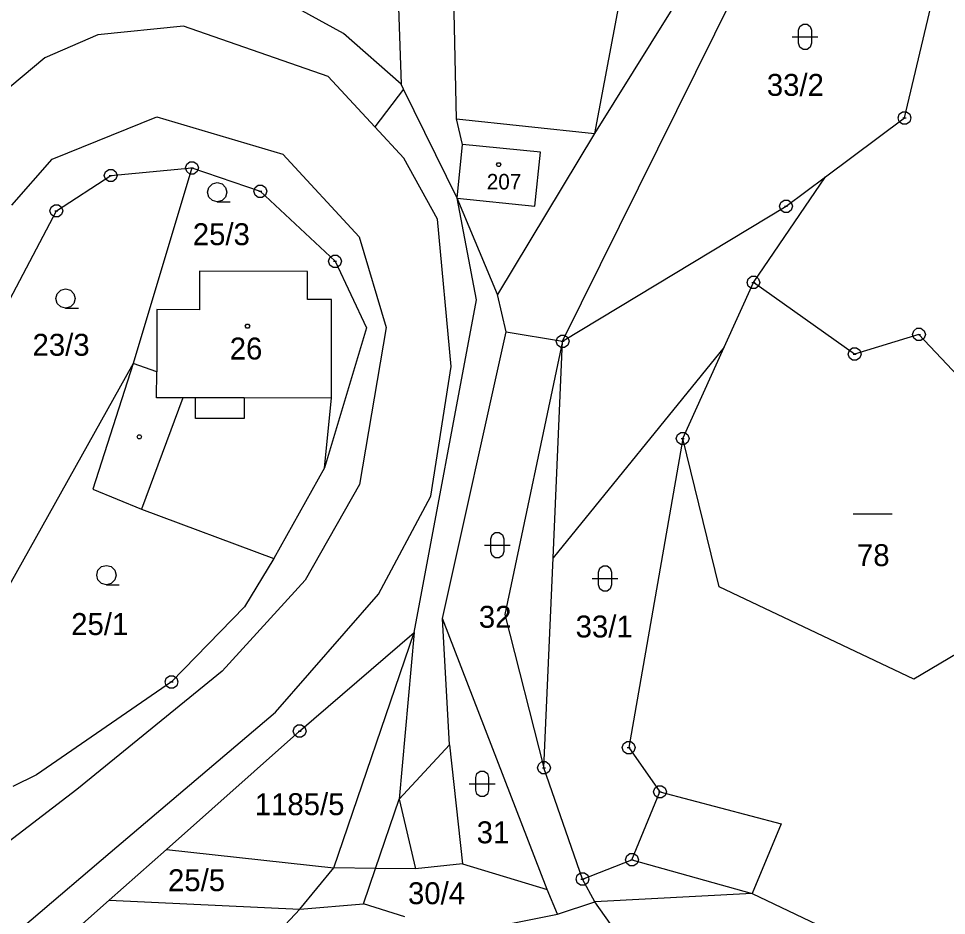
# Model space of a CAD drawing. Extents: x -694465 to -690527, y -983694 to -978978.
# Drawn here: x -691805.9 to -691734, y -981057 to -980987.5 of the extents above; entities that cross this region are included whole.
import ezdxf

# ---------------------------------------------------------------- set-up
doc = ezdxf.new("R2010")
doc.units = 0
for name, color, linetype in [('Vrstva 1', 7, 'Continuous'), ('Vrstva 18', 7, 'Continuous'), ('Vrstva 19', 7, 'Continuous'), ('Vrstva 24', 7, 'Continuous'), ('Vrstva 25', 7, 'Continuous')]:
    doc.layers.add(name, color=color, linetype=linetype)

msp = doc.modelspace()

# ---------------------------------------------------------------- linework, layer by layer
at = {"layer": 'Vrstva 1'}
for points in [[(-691753.27, -980956.49), (-691754.479, -980963.964), (-691753.869, -980984.579), (-691761.25, -980996.4)], [(-691757.32, -980975.53), (-691761.25, -980996.4)], [(-691776.7, -980979.2), (-691776.23, -980992.59)], [(-691771.95, -980995.28), (-691772.18, -980984.63)], [(-691780.69, -980988.65), (-691785.28, -980986.14)], [(-691763.71, -981012.51), (-691750.43, -980985.69)], [(-691737.21, -980995.2), (-691735.16, -980986.59)], [(-691793.09, -980988.08), (-691799.74, -980988.76)], [(-691781.88, -980991.99), (-691793.09, -980988.08)], [(-691799.74, -980988.76), (-691803.84, -980990.55)], [(-691776.23, -980992.59), (-691780.69, -980988.65)], [(-691803.84, -980990.55), (-691809.14, -980994.97)], [(-691778.265, -980995.895), (-691781.88, -980991.99)], [(-691776.037, -980992.983), (-691776.23, -980992.59)], [(-691776.037, -980992.983), (-691778.265, -980995.895)], [(-691771.9, -981001.43), (-691776.037, -980992.983)], [(-691803.27, -980998.4), (-691795.18, -980995.12)], [(-691795.18, -980995.12), (-691785.4, -980998.02)], [(-691771.47, -980997.25), (-691771.95, -980995.28)], [(-691771.95, -980995.28), (-691761.25, -980996.4)], [(-691743.34, -980999.77), (-691737.21, -980995.2)], [(-691776.03, -980998.31), (-691778.265, -980995.895)], [(-691761.25, -980996.4), (-691768.75, -981008.88)], [(-691771.9, -981001.43), (-691771.47, -980997.25)], [(-691765.44, -980997.86), (-691771.47, -980997.25)], [(-691765.86, -981002.04), (-691765.44, -980997.86)], [(-691806.4, -981001.96), (-691803.27, -980998.4)], [(-691785.4, -980998.02), (-691779.48, -981004.42)], [(-691773.41, -981003.05), (-691776.03, -980998.31)], [(-691809.08, -981022.44), (-691807.08, -981010.25), (-691802.95, -981002.4), (-691798.74, -980999.66), (-691792.45, -980999.07)], [(-691792.45, -980999.07), (-691797, -981014.23)], [(-691792.45, -980999.07), (-691787.15, -981000.88)], [(-691748.92, -981007.95), (-691743.34, -980999.77)], [(-691746.39, -981002.05), (-691743.34, -980999.77)], [(-691787.15, -981000.88), (-691781.35, -981006.31), (-691778.92, -981011.46), (-691782.16, -981022.32)], [(-691768.75, -981008.88), (-691771.9, -981001.43)], [(-691771.9, -981001.43), (-691765.86, -981002.04)], [(-691770.4, -981009.3), (-691771.9, -981001.43)], [(-691763.71, -981012.51), (-691746.39, -981002.05)], [(-691772.36, -981014.46), (-691773.41, -981003.05)], [(-691779.48, -981004.42), (-691777.39, -981011.44)], [(-691791.85, -981007.08), (-691791.86, -981010.06)], [(-691783.49, -981007.09), (-691791.85, -981007.08)], [(-691783.49, -981009.28), (-691783.49, -981007.09)], [(-691751.188, -981012.953), (-691748.92, -981007.95)], [(-691741.08, -981013.5), (-691748.92, -981007.95)], [(-691781.63, -981009.28), (-691783.49, -981009.28)], [(-691781.64, -981016.91), (-691781.63, -981009.28)], [(-691775.21, -981035.08), (-691770.4, -981009.3)], [(-691768.09, -981011.77), (-691768.75, -981008.88)], [(-691791.86, -981010.06), (-691795.18, -981010.05)], [(-691795.18, -981010.05), (-691795.18, -981014.87)], [(-691777.39, -981011.44), (-691779.46, -981023.61)], [(-691773.02, -981034), (-691768.09, -981011.77)], [(-691768.09, -981011.77), (-691763.71, -981012.51)], [(-691736.09, -981011.98), (-691741.08, -981013.5)], [(-691725.69, -981023), (-691736.09, -981011.98)], [(-691763.71, -981012.51), (-691768.2, -981033.672), (-691765.16, -981045.56)], [(-691764.446, -981029.294), (-691763.71, -981012.51)], [(-691751.188, -981012.953), (-691764.446, -981029.294)], [(-691754.4, -981020.04), (-691751.188, -981012.953)], [(-691797, -981014.23), (-691807.08, -981032.26)], [(-691797, -981014.23), (-691800.14, -981023.98)], [(-691795.18, -981014.87), (-691797, -981014.23)], [(-691795.19, -981016.89), (-691795.18, -981014.87)], [(-691773.92, -981024.52), (-691772.36, -981014.46)], [(-691793.15, -981016.89), (-691796.35, -981025.53)], [(-691793.15, -981016.89), (-691795.19, -981016.89)], [(-691792.16, -981016.9), (-691793.15, -981016.89)], [(-691788.4, -981016.9), (-691792.16, -981016.9)], [(-691792.16, -981018.49), (-691792.16, -981016.9)], [(-691781.64, -981016.91), (-691788.4, -981016.9)], [(-691788.4, -981016.9), (-691788.4, -981018.49)], [(-691782.16, -981022.32), (-691781.64, -981016.91)], [(-691788.4, -981018.49), (-691792.16, -981018.49)], [(-691754.4, -981020.04), (-691758.59, -981043.99)], [(-691751.59, -981031.54), (-691754.4, -981020.04)], [(-691782.16, -981022.32), (-691786.09, -981029.35)], [(-691779.46, -981023.61), (-691783.68, -981031.02)], [(-691800.14, -981023.98), (-691796.35, -981025.53)], [(-691777.99, -981032.1), (-691773.92, -981024.52)], [(-691796.35, -981025.53), (-691786.09, -981029.35)], [(-691786.09, -981029.35), (-691788.36, -981033.08)], [(-691765.16, -981045.56), (-691764.446, -981029.294)], [(-691783.68, -981031.02), (-691790.1, -981038.06)], [(-691736.5, -981038.69), (-691751.59, -981031.54)], [(-691785.98, -981041.25), (-691777.99, -981032.1)], [(-691788.36, -981033.08), (-691794.03, -981038.91), (-691804.49, -981046.11)], [(-691726.14, -981032.57), (-691736.5, -981038.69)], [(-691764.9, -981054.98), (-691773.02, -981034)], [(-691772.47, -981043.77), (-691773.02, -981034)], [(-691784.1, -981042.71), (-691775.21, -981035.08)], [(-691781.45, -981053.31), (-691775.21, -981035.08)], [(-691775.21, -981035.08), (-691776.39, -981047.99)], [(-691790.1, -981038.06), (-691801.38, -981047.23)], [(-691798.78, -981052.13), (-691785.98, -981041.25)], [(-691794.42, -981051.88), (-691784.1, -981042.71)], [(-691776.39, -981047.99), (-691772.47, -981043.77)], [(-691772.47, -981043.77), (-691771.47, -981053.01)], [(-691758.59, -981043.99), (-691756.17, -981047.42)], [(-691762.17, -981054.18), (-691765.16, -981045.56)], [(-691804.49, -981046.11), (-691806.34, -981047.02)], [(-691801.38, -981047.23), (-691816.93, -981059.15)], [(-691758.34, -981052.68), (-691756.17, -981047.42)], [(-691756.17, -981047.42), (-691746.76, -981049.89)], [(-691778.21, -981053.36), (-691776.39, -981047.99)], [(-691776.39, -981047.99), (-691775.12, -981053.4)], [(-691746.76, -981049.89), (-691749.02, -981055.3)], [(-691811.06, -981062.57), (-691798.78, -981052.13)], [(-691798.87, -981055.81), (-691794.42, -981051.88)], [(-691794.42, -981051.88), (-691781.45, -981053.31)], [(-691771.47, -981053.01), (-691775.12, -981053.4)], [(-691771.47, -981053.01), (-691764.9, -981054.98)], [(-691762.17, -981054.18), (-691758.34, -981052.68)], [(-691758.34, -981052.68), (-691749.02, -981055.3)], [(-691784.08, -981056.52), (-691781.45, -981053.31)], [(-691778.21, -981053.36), (-691781.45, -981053.31)], [(-691779.14, -981056.09), (-691778.21, -981053.36)], [(-691775.12, -981053.4), (-691778.21, -981053.36)], [(-691761.21, -981055.95), (-691762.17, -981054.18)], [(-691764.11, -981056.9), (-691764.9, -981054.98)], [(-691749.02, -981055.3), (-691761.21, -981055.95)], [(-691749.02, -981055.3), (-691722.7, -981067.85)], [(-691809.71, -981065.43), (-691798.87, -981055.81)], [(-691798.87, -981055.81), (-691784.08, -981056.52)], [(-691784.08, -981056.52), (-691779.14, -981056.09)], [(-691775.94, -981057.1), (-691779.14, -981056.09)], [(-691764.11, -981056.9), (-691761.21, -981055.95)], [(-691759.15, -981058.87), (-691761.21, -981055.95)], [(-691784.08, -981056.52), (-691791.64, -981064.58)], [(-691774.08, -981058.89), (-691764.11, -981056.9)]]:
    msp.add_lwpolyline(points, dxfattribs=at)
at = {"layer": 'Vrstva 24'}
for points in [[(-691737.056, -980994.724), (-691736.806, -980994.906), (-691736.71, -980995.2), (-691736.806, -980995.494), (-691737.056, -980995.676), (-691737.364, -980995.676), (-691737.614, -980995.494), (-691737.71, -980995.2), (-691737.614, -980994.906), (-691737.364, -980994.724)], [(-691798.586, -980999.184), (-691798.336, -980999.366), (-691798.24, -980999.66), (-691798.336, -980999.954), (-691798.586, -981000.136), (-691798.894, -981000.136), (-691799.144, -980999.954), (-691799.24, -980999.66), (-691799.144, -980999.366), (-691798.894, -980999.184)], [(-691792.296, -980998.594), (-691792.046, -980998.776), (-691791.95, -980999.07), (-691792.046, -980999.364), (-691792.296, -980999.546), (-691792.604, -980999.546), (-691792.854, -980999.364), (-691792.95, -980999.07), (-691792.854, -980998.776), (-691792.604, -980998.594)], [(-691786.996, -981000.404), (-691786.746, -981000.586), (-691786.65, -981000.88), (-691786.746, -981001.174), (-691786.996, -981001.356), (-691787.304, -981001.356), (-691787.554, -981001.174), (-691787.65, -981000.88), (-691787.554, -981000.586), (-691787.304, -981000.404)], [(-691802.796, -981001.924), (-691802.546, -981002.106), (-691802.45, -981002.4), (-691802.546, -981002.694), (-691802.796, -981002.876), (-691803.104, -981002.876), (-691803.354, -981002.694), (-691803.45, -981002.4), (-691803.354, -981002.106), (-691803.104, -981001.924)], [(-691746.236, -981001.574), (-691745.986, -981001.756), (-691745.89, -981002.05), (-691745.986, -981002.344), (-691746.236, -981002.526), (-691746.544, -981002.526), (-691746.794, -981002.344), (-691746.89, -981002.05), (-691746.794, -981001.756), (-691746.544, -981001.574)], [(-691781.196, -981005.834), (-691780.946, -981006.016), (-691780.85, -981006.31), (-691780.946, -981006.604), (-691781.196, -981006.786), (-691781.504, -981006.786), (-691781.754, -981006.604), (-691781.85, -981006.31), (-691781.754, -981006.016), (-691781.504, -981005.834)], [(-691748.766, -981007.474), (-691748.516, -981007.656), (-691748.42, -981007.95), (-691748.516, -981008.244), (-691748.766, -981008.426), (-691749.074, -981008.426), (-691749.324, -981008.244), (-691749.42, -981007.95), (-691749.324, -981007.656), (-691749.074, -981007.474)], [(-691735.936, -981011.504), (-691735.686, -981011.686), (-691735.59, -981011.98), (-691735.686, -981012.274), (-691735.936, -981012.456), (-691736.244, -981012.456), (-691736.494, -981012.274), (-691736.59, -981011.98), (-691736.494, -981011.686), (-691736.244, -981011.504)], [(-691763.556, -981012.034), (-691763.306, -981012.216), (-691763.21, -981012.51), (-691763.306, -981012.804), (-691763.556, -981012.986), (-691763.864, -981012.986), (-691764.114, -981012.804), (-691764.21, -981012.51), (-691764.114, -981012.216), (-691763.864, -981012.034)], [(-691740.926, -981013.024), (-691740.676, -981013.206), (-691740.58, -981013.5), (-691740.676, -981013.794), (-691740.926, -981013.976), (-691741.234, -981013.976), (-691741.484, -981013.794), (-691741.58, -981013.5), (-691741.484, -981013.206), (-691741.234, -981013.024)], [(-691754.246, -981019.564), (-691753.996, -981019.746), (-691753.9, -981020.04), (-691753.996, -981020.334), (-691754.246, -981020.516), (-691754.554, -981020.516), (-691754.804, -981020.334), (-691754.9, -981020.04), (-691754.804, -981019.746), (-691754.554, -981019.564)], [(-691793.876, -981038.434), (-691793.626, -981038.616), (-691793.53, -981038.91), (-691793.626, -981039.204), (-691793.876, -981039.386), (-691794.184, -981039.386), (-691794.434, -981039.204), (-691794.53, -981038.91), (-691794.434, -981038.616), (-691794.184, -981038.434)], [(-691783.946, -981042.234), (-691783.696, -981042.416), (-691783.6, -981042.71), (-691783.696, -981043.004), (-691783.946, -981043.186), (-691784.254, -981043.186), (-691784.504, -981043.004), (-691784.6, -981042.71), (-691784.504, -981042.416), (-691784.254, -981042.234)], [(-691758.436, -981043.514), (-691758.186, -981043.696), (-691758.09, -981043.99), (-691758.186, -981044.284), (-691758.436, -981044.466), (-691758.744, -981044.466), (-691758.994, -981044.284), (-691759.09, -981043.99), (-691758.994, -981043.696), (-691758.744, -981043.514)], [(-691765.006, -981045.084), (-691764.756, -981045.266), (-691764.66, -981045.56), (-691764.756, -981045.854), (-691765.006, -981046.036), (-691765.314, -981046.036), (-691765.564, -981045.854), (-691765.66, -981045.56), (-691765.564, -981045.266), (-691765.314, -981045.084)], [(-691756.016, -981046.944), (-691755.766, -981047.126), (-691755.67, -981047.42), (-691755.766, -981047.714), (-691756.016, -981047.896), (-691756.324, -981047.896), (-691756.574, -981047.714), (-691756.67, -981047.42), (-691756.574, -981047.126), (-691756.324, -981046.944)], [(-691758.186, -981052.204), (-691757.936, -981052.386), (-691757.84, -981052.68), (-691757.936, -981052.974), (-691758.186, -981053.156), (-691758.494, -981053.156), (-691758.744, -981052.974), (-691758.84, -981052.68), (-691758.744, -981052.386), (-691758.494, -981052.204)], [(-691762.016, -981053.704), (-691761.766, -981053.886), (-691761.67, -981054.18), (-691761.766, -981054.474), (-691762.016, -981054.656), (-691762.324, -981054.656), (-691762.574, -981054.474), (-691762.67, -981054.18), (-691762.574, -981053.886), (-691762.324, -981053.704)]]:
    msp.add_lwpolyline(points, close=True, dxfattribs=at)
for points in [[(-691737.329, -980995.2), (-691737.09, -980995.2)], [(-691792.569, -980999.07), (-691792.33, -980999.07)], [(-691798.859, -980999.66), (-691798.62, -980999.66)], [(-691787.269, -981000.88), (-691787.03, -981000.88)], [(-691746.509, -981002.05), (-691746.27, -981002.05)], [(-691803.069, -981002.4), (-691802.83, -981002.4)], [(-691781.469, -981006.31), (-691781.23, -981006.31)], [(-691749.039, -981007.95), (-691748.8, -981007.95)], [(-691736.209, -981011.98), (-691735.97, -981011.98)], [(-691763.829, -981012.51), (-691763.59, -981012.51)], [(-691741.199, -981013.5), (-691740.96, -981013.5)], [(-691754.519, -981020.04), (-691754.28, -981020.04)], [(-691794.149, -981038.91), (-691793.91, -981038.91)], [(-691784.219, -981042.71), (-691783.98, -981042.71)], [(-691758.709, -981043.99), (-691758.47, -981043.99)], [(-691765.279, -981045.56), (-691765.04, -981045.56)], [(-691756.289, -981047.42), (-691756.05, -981047.42)], [(-691758.459, -981052.68), (-691758.22, -981052.68)], [(-691762.289, -981054.18), (-691762.05, -981054.18)]]:
    msp.add_lwpolyline(points, dxfattribs=at)
at = {"layer": 'Vrstva 25'}
for points in [[(-691745.42, -980988.41), (-691745.325, -980988.116), (-691745.075, -980987.934), (-691744.765, -980987.934), (-691744.515, -980988.116), (-691744.42, -980988.41), (-691744.42, -980989.41), (-691744.515, -980989.704), (-691744.765, -980989.886), (-691745.075, -980989.886), (-691745.325, -980989.704), (-691745.42, -980989.41)], [(-691768.583, -980998.668), (-691768.495, -980998.82), (-691768.583, -980998.972), (-691768.757, -980998.972), (-691768.845, -980998.82), (-691768.757, -980998.668)], [(-691788.053, -981011.188), (-691787.965, -981011.34), (-691788.053, -981011.492), (-691788.227, -981011.492), (-691788.315, -981011.34), (-691788.227, -981011.188)], [(-691796.443, -981019.768), (-691796.355, -981019.92), (-691796.443, -981020.072), (-691796.617, -981020.072), (-691796.705, -981019.92), (-691796.617, -981019.768)], [(-691769.28, -981027.81), (-691769.185, -981027.516), (-691768.935, -981027.334), (-691768.625, -981027.334), (-691768.375, -981027.516), (-691768.28, -981027.81), (-691768.28, -981028.81), (-691768.375, -981029.104), (-691768.625, -981029.286), (-691768.935, -981029.286), (-691769.185, -981029.104), (-691769.28, -981028.81)], [(-691760.92, -981030.39), (-691760.825, -981030.096), (-691760.575, -981029.914), (-691760.265, -981029.914), (-691760.015, -981030.096), (-691759.92, -981030.39), (-691759.92, -981031.39), (-691760.015, -981031.684), (-691760.265, -981031.866), (-691760.575, -981031.866), (-691760.825, -981031.684), (-691760.92, -981031.39)], [(-691770.45, -981046.3), (-691770.355, -981046.006), (-691770.105, -981045.824), (-691769.795, -981045.824), (-691769.545, -981046.006), (-691769.45, -981046.3), (-691769.45, -981047.3), (-691769.545, -981047.594), (-691769.795, -981047.776), (-691770.105, -981047.776), (-691770.355, -981047.594), (-691770.45, -981047.3)]]:
    msp.add_lwpolyline(points, close=True, dxfattribs=at)
for points in [[(-691745.92, -980988.91), (-691743.92, -980988.91)], [(-691790.49, -981001.71), (-691790.865, -981001.609), (-691791.139, -981001.335), (-691791.24, -981000.96), (-691791.139, -981000.585), (-691790.865, -981000.311), (-691790.49, -981000.21), (-691790.115, -981000.311), (-691789.841, -981000.585), (-691789.74, -981000.96), (-691789.841, -981001.335), (-691790.115, -981001.609), (-691790.49, -981001.71), (-691789.49, -981001.711)], [(-691802.24, -981009.95), (-691802.615, -981009.849), (-691802.889, -981009.575), (-691802.99, -981009.2), (-691802.889, -981008.825), (-691802.615, -981008.551), (-691802.24, -981008.45), (-691801.865, -981008.551), (-691801.591, -981008.825), (-691801.49, -981009.2), (-691801.591, -981009.575), (-691801.865, -981009.849), (-691802.24, -981009.95), (-691801.24, -981009.951)], [(-691741.18, -981025.89), (-691738.18, -981025.89)], [(-691769.78, -981028.31), (-691767.78, -981028.31)], [(-691799.08, -981031.37), (-691799.455, -981031.269), (-691799.729, -981030.995), (-691799.83, -981030.62), (-691799.729, -981030.245), (-691799.455, -981029.971), (-691799.08, -981029.87), (-691798.705, -981029.971), (-691798.431, -981030.245), (-691798.33, -981030.62), (-691798.431, -981030.995), (-691798.705, -981031.269), (-691799.08, -981031.37), (-691798.08, -981031.371)], [(-691761.42, -981030.89), (-691759.42, -981030.89)], [(-691770.95, -981046.8), (-691768.95, -981046.8)]]:
    msp.add_lwpolyline(points, dxfattribs=at)

# ---------------------------------------------------------------- texts
at = {"layer": 'Vrstva 18'}
for s, p in [('33/2', (-691747.883, -980993.49)), ('25/3', (-691792.381, -981005.06)), ('23/3', (-691804.802, -981013.63)), ('78', (-691740.895, -981029.93)), ('32', (-691770.206, -981034.71)), ('25/1', (-691801.806, -981035.27)), ('33/1', (-691762.703, -981035.46)), ('1185/5', (-691787.577, -981049.23)), ('31', (-691770.374, -981051.41)), ('25/5', (-691794.301, -981055.12)), ('30/4', (-691775.698, -981056.13))]:
    msp.add_text(s, height=1.7, dxfattribs=at).set_placement(p)
at = {"layer": 'Vrstva 19'}
for s, height, p in [('207', 1.2, (-691769.592, -981000.74)), ('26', 1.7, (-691789.519, -981013.92))]:
    msp.add_text(s, height=height, dxfattribs=at).set_placement(p)

doc.saveas('drawing.dxf')
